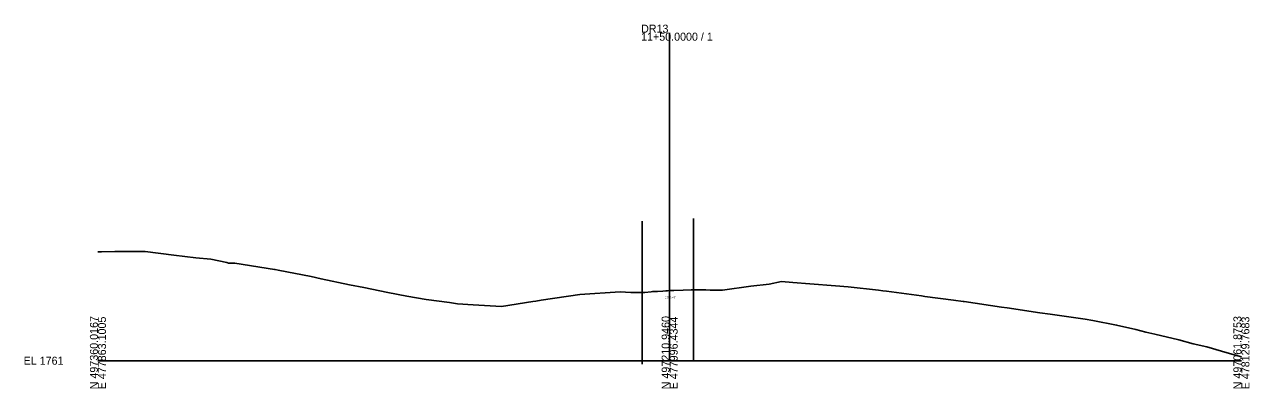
# Model space of a CAD drawing. Extents: x -26 to 403, y -10 to 2160.
# Drawn here: x -25.7 to 402.8, y 1490.3 to 1617.4 of the extents above; entities that cross this region are included whole.
import ezdxf

# ---------------------------------------------------------------- set-up
doc = ezdxf.new("R2010")
doc.units = 0
for name, color, linetype in [('Exist Cross Section Cell', 7, 'Continuous'), ('Exist XS Center Line Elevation Label', 7, 'Continuous'), ('Exist XS Ground Line', 7, 'Continuous'), ('Scratch_Level_1', 7, 'Continuous'), ('Scratch_Level_5', 7, 'Continuous')]:
    doc.layers.add(name, color=color, linetype=linetype)

msp = doc.modelspace()

# ---------------------------------------------------------------- linework, layer by layer
at = {"layer": 'Exist Cross Section Cell'}
for p, q in [((200, 1500), (200, 1614.57)), ((0, 1500), (200, 1500)), ((200, 1500), (400, 1500))]:
    msp.add_line(p, q, dxfattribs=at)
at = {"layer": 'Exist XS Ground Line'}
msp.add_lwpolyline([(0, 1537.98), (1.23, 1538.05), (5.92, 1538.18), (15.52, 1538.19), (16.48, 1538.1), (26.49, 1536.91), (34.3, 1535.91), (39.45, 1535.42), (45.09, 1534.27), (45.68, 1534.04), (46.26, 1534.03), (46.61, 1534.03), (47.19, 1534.02), (47.86, 1534.02), (61.71, 1531.91), (62.02, 1531.85), (63.02, 1531.65), (74.55, 1529.37), (78.03, 1528.56), (87.97, 1526.51), (93.03, 1525.56), (101.39, 1523.84), (108.03, 1522.58), (114.81, 1521.4), (123.03, 1520.29), (125.77, 1519.9), (131.27, 1519.5), (141.21, 1518.92), (152.13, 1520.68), (153.22, 1520.85), (155.06, 1521.15), (168.57, 1523.14), (182.68, 1524.08), (186.38, 1523.78), (186.76, 1523.78), (190.37, 1523.78), (190.75, 1523.79), (191.29, 1523.83), (193.5, 1524.07), (193.94, 1524.12), (194.34, 1524.14), (195.72, 1524.2), (197.64, 1524.32), (198.69, 1524.39), (199.19, 1524.43), (200, 1524.47), (200.64, 1524.51), (201.04, 1524.53), (201.42, 1524.55), (204.73, 1524.65), (207.49, 1524.7), (208.3, 1524.72), (212.02, 1524.73), (212.67, 1524.7), (214.2, 1524.68), (218.49, 1524.67), (228.45, 1526.02), (234.85, 1526.78), (239.11, 1527.63), (243.06, 1527.27), (249, 1526.82), (258.06, 1526.19), (262.41, 1525.81), (273.06, 1524.59), (274.53, 1524.45), (275.83, 1524.26), (288.07, 1522.62), (289.25, 1522.45), (299.32, 1521.13), (302.67, 1520.7), (303.07, 1520.65), (316.09, 1518.75), (318.07, 1518.47), (329.51, 1516.71), (333.07, 1516.25), (342.93, 1514.85), (345.36, 1514.48), (348.08, 1514.04), (356.35, 1512.47), (363.08, 1510.86), (366.61, 1509.97), (369.77, 1509.27), (378.08, 1507.25), (383.19, 1505.93), (387.86, 1504.82), (393.08, 1503.35), (396.61, 1502.34), (400, 1501.41)], dxfattribs=at)
at = {"layer": 'Scratch_Level_1'}
for p, q in [((190.37, 1548.78), (190.37, 1498.78)), ((208.3, 1549.72), (208.3, 1499.72))]:
    msp.add_line(p, q, dxfattribs=at)
at = {"layer": 'Scratch_Level_5'}
msp.add_lwpolyline([(45.68, 1534.04), (47.86, 1534.02), (61.71, 1531.91), (62.02, 1531.85), (63.02, 1531.65), (74.55, 1529.37), (78.03, 1528.56), (87.97, 1526.51), (93.03, 1525.56), (101.39, 1523.84), (108.03, 1522.58), (114.81, 1521.4), (123.03, 1520.29), (125.77, 1519.9), (131.27, 1519.5), (141.21, 1518.92), (152.13, 1520.68), (153.22, 1520.85), (155.06, 1521.15), (168.57, 1523.14), (182.68, 1524.08), (186.38, 1523.78), (186.76, 1523.78), (190.37, 1523.78), (190.75, 1523.79), (191.29, 1523.83), (193.5, 1524.07), (193.94, 1524.12), (194.34, 1524.14), (195.72, 1524.2), (197.64, 1524.32), (198.69, 1524.39), (199.19, 1524.43), (200, 1524.47), (200.64, 1524.51), (201.04, 1524.53), (201.42, 1524.55), (204.73, 1524.65), (207.49, 1524.7), (208.3, 1524.72), (212.02, 1524.73), (212.67, 1524.7), (214.2, 1524.68), (218.49, 1524.67), (228.45, 1526.02), (234.85, 1526.78), (239.11, 1527.63), (243.06, 1527.27), (249, 1526.82), (258.06, 1526.19), (262.41, 1525.81), (273.06, 1524.59), (274.53, 1524.45), (275.83, 1524.26), (288.07, 1522.62), (289.25, 1522.45), (299.32, 1521.13), (302.67, 1520.7), (303.07, 1520.65), (316.09, 1518.75), (318.07, 1518.47), (329.51, 1516.71), (333.07, 1516.25), (342.93, 1514.85), (345.36, 1514.48), (348.08, 1514.04), (356.35, 1512.47), (363.08, 1510.86), (366.61, 1509.97), (369.77, 1509.27), (378.08, 1507.25), (383.19, 1505.93), (387.86, 1504.82), (393.08, 1503.35), (396.61, 1502.34), (400, 1501.41)], dxfattribs=at)

# ---------------------------------------------------------------- texts
at = {"layer": 'Exist Cross Section Cell'}
for s, p in [('DR13', (190, 1614.57)), ('11+50.0000 / 1', (190, 1611.77)), ('EL 1761', (-26, 1498.6))]:
    msp.add_text(s, height=2.8, dxfattribs=at).set_placement(p)
for s, p in [('N 497360.0167', (0, 1490)), ('E 477863.1005', (2.8, 1490)), ('N 497210.9460', (200, 1490)), ('E 477996.4344', (202.8, 1490)), ('N 497061.8753', (400, 1490)), ('E 478129.7683', (402.8, 1490))]:
    msp.add_text(s, height=2.8, rotation=90, dxfattribs=at).set_placement(p)
at = {"layer": 'Exist XS Center Line Elevation Label'}
msp.add_text('1785.47', height=0.75, dxfattribs=at).set_placement((198.29, 1521.72))

doc.saveas('drawing.dxf')
